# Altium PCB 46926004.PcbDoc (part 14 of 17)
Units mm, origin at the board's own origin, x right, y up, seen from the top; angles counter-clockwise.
Board outline 250 x 200 mm, 6 copper layers (Top Layer, INT1_GND, INT2_SIG, INT3_SIG, INT4_GND, Bottom Layer), stack 1.71 mm thick; 1450 components, 1293 nets, 5656 pads, 2307 vias.
Unrouted connection lines stored in the file: 2.
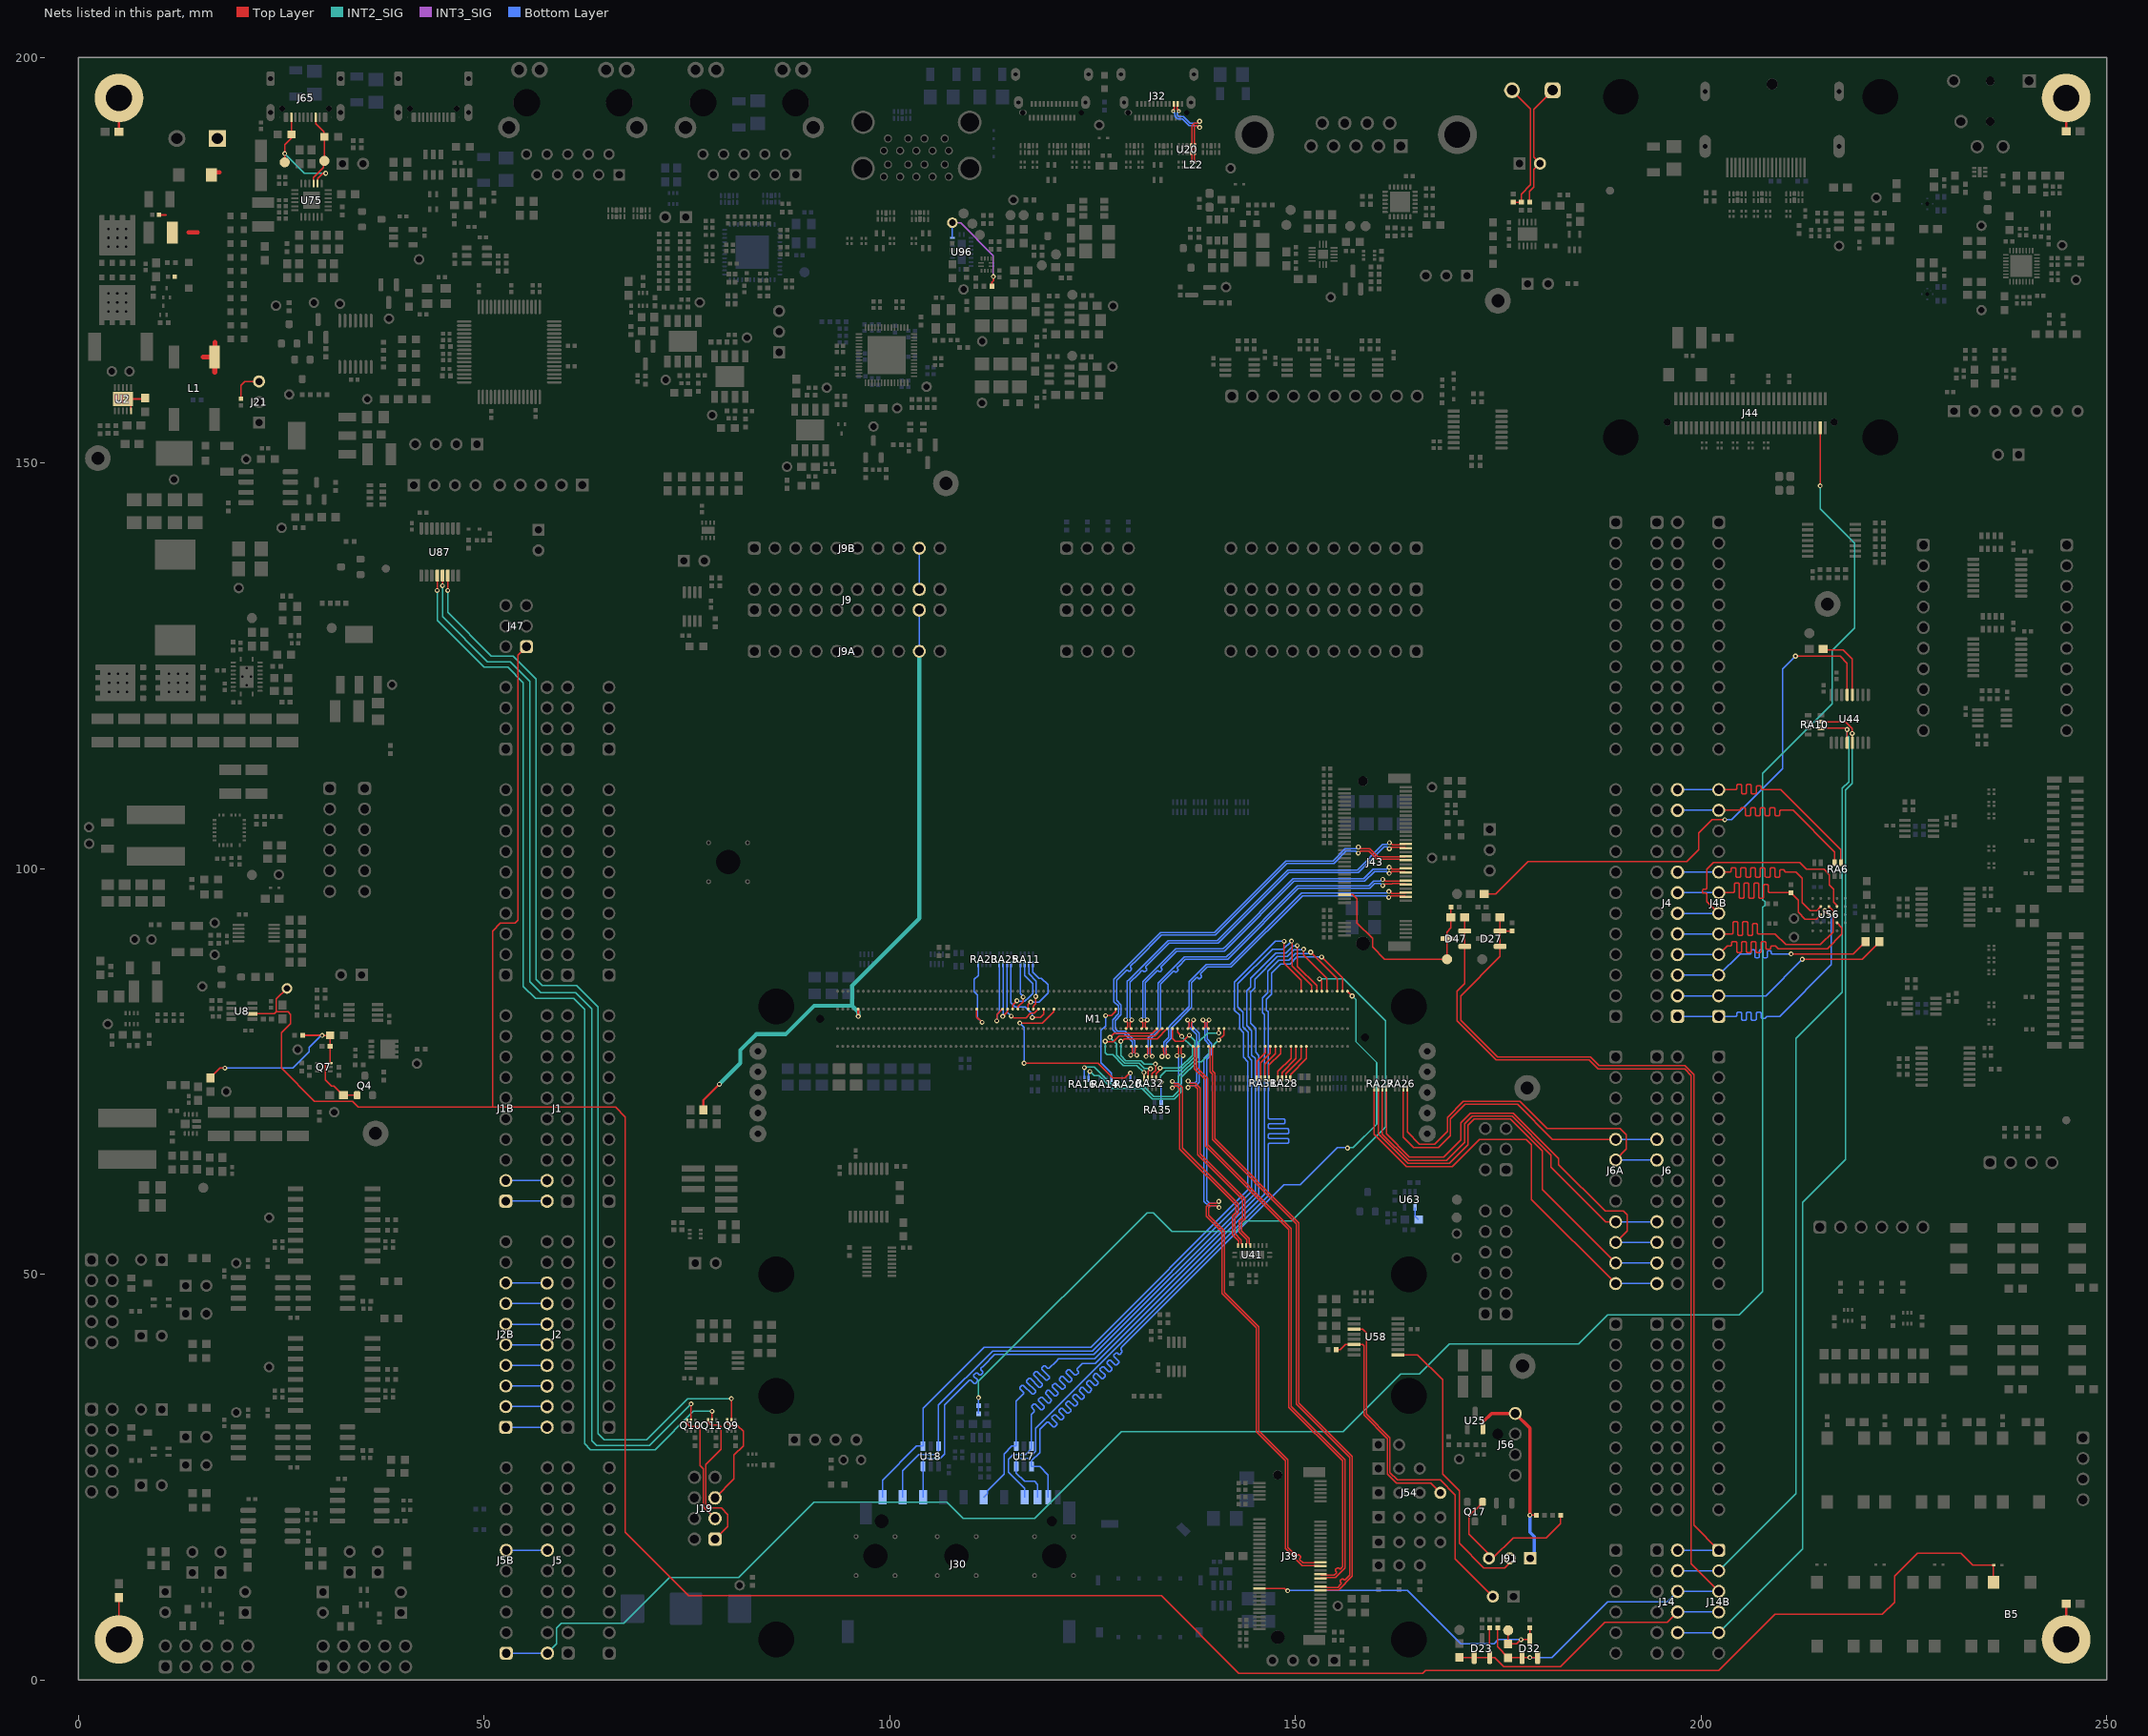
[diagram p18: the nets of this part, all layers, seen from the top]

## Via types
v1: diameter 0.6, hole 0.3, Top Layer to Bottom Layer, tented both sides, 2171 vias
v2: diameter 0.6, hole 0.3, Top Layer to Bottom Layer, 48 vias
v3: diameter 1, hole 0.5, Top Layer to Bottom Layer, tented both sides, 37 vias
v4: diameter 0.5, hole 0.2, Top Layer to Bottom Layer, tented both sides, 34 vias
v5: diameter 0.6, hole 0.3, Top Layer to Bottom Layer, tented bottom, 17 vias

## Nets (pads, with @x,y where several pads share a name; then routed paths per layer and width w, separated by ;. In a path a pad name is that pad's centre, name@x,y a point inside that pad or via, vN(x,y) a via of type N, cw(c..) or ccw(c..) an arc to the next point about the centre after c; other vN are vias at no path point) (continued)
OSPI_1_IO6_JMP: J4.21 J4B.11 RA6.4 | length 29.6
  Top Layer w0.15: J4B.11@202.17,107.2 204.69,107.2 204.765,107.2 204.885,107.32 204.885,107.408 205.005,107.528 205.365,107.528 205.485,107.408 205.485,106.638 205.605,106.518 205.965,106.518 206.085,106.638 206.085,107.408 206.205,107.528 206.565,107.528 206.685,107.408 206.685,106.638 206.805,106.518 207.165,106.518 207.285,106.638 207.285,107.408 207.405,107.528 207.765,107.528 207.885,107.408 207.885,106.638 208.005,106.518 208.365,106.518 208.485,106.638 208.485,107.408 208.605,107.528 208.965,107.528 209.085,107.408 209.085,106.655 209.205,106.535 209.565,106.535 209.685,106.655 209.685,107.08 209.805,107.2 210.895,107.2 211.325,107.2 216.45,102.075 RA6.4@216.45,100.725
  Bottom Layer w0.15: J4.21@197.09,107.2 J4B.11@202.17,107.2
OSPI_1_IO7: M1.B73 RA23.4 | length 9.7
  Top Layer w0.15: M1.B73@110.712,82.7 110.712,81.747 v1(111.391,81.068)
  Bottom Layer w0.15: RA23.4@110.9,88.25 110.9,86.862 110.4,86.362 110.4,84.848 110.827,84.421 110.827,81.632 v1(111.391,81.068)
OSPI_1_IO7_JMP: J4.23 J4B.12 RA6.3 | length 29.5
  Top Layer w0.15: J4B.12@202.17,109.74 204.19,109.74 204.265,109.74 204.385,109.86 204.385,110.266 204.505,110.386 204.865,110.386 204.985,110.266 204.985,109.353 205.105,109.233 205.465,109.233 205.585,109.353 205.585,110.266 205.705,110.386 206.065,110.386 206.185,110.266 206.185,109.353 206.305,109.233 206.665,109.233 206.785,109.353 206.785,110.097 206.905,110.217 207.265,110.217 207.385,110.097 207.385,109.86 207.505,109.74 208.592,109.74 209.798,109.74 217.213,102.325 217.213,100.762 RA6.3@217.25,100.725
  Bottom Layer w0.15: J4.23@197.09,109.74 J4B.12@202.17,109.74
PCIE/USB3_SEL: R194.2 U63.4 | length 1.7
  Bottom Layer w0.15: U63.4@164.75,58.248 164.75,57.183 165.175,56.758 R194.2@165.185,56.758
PCIE_1_CLK_N: J43.53 M1.D37 | length 43.5
  Top Layer w0.15: v1(133.548,76.847) 133.548,76.935 133.773,77.16 133.773,77.415 133.74,77.449 133.74,77.909 133.572,78.077 M1.D37@133.572,78.1 ; v1(161.512,97.2) 161.634,97.2 161.884,96.95 162.812,96.95 162.837,96.975 163.525,96.975 J43.53@163.6,97.05
  Bottom Layer w0.15: v1(133.548,76.847) 133.548,76.935 133.773,77.16 133.773,78.605 134.349,79.181 134.349,80.459 134.734,80.844 ; 134.734,80.865 134.734,80.844 ; v1(161.512,97.2) 161.422,97.2 161.199,96.977 156.578,96.977 156.576,96.975 150.748,96.975 141.963,88.19 139.001,88.19 136.91,86.099 136.91,83.02 134.734,80.844
PCIE_1_CLK_P: J43.55 M1.D36 | length 43.5
  Top Layer w0.15: M1.D36@134.207,78.1 134.207,78.077 134.04,77.909 134.04,77.574 134.073,77.54 134.073,77.16 134.298,76.935 v1(134.298,76.847) ; v1(161.5,96.45) 161.622,96.45 161.822,96.65 162.812,96.65 162.837,96.625 163.525,96.625 J43.55@163.6,96.55
  Bottom Layer w0.15: v1(134.298,76.847) 134.298,76.935 134.073,77.16 134.073,78.481 134.649,79.056 134.649,80.335 137.21,82.896 137.21,85.975 137.405,86.17 137.811,86.576 137.953,86.576 138.076,86.452 138.218,86.452 138.43,86.665 138.43,86.806 138.306,86.93 138.306,87.071 138.888,87.653 139.125,87.89 142.087,87.89 150.872,96.675 156.7,96.675 156.702,96.677 161.187,96.677 161.414,96.45 v1(161.5,96.45)
PCIE_1_CLKREQ: M1.C37 RA32.4 | length 15.6
  Top Layer w0.15: v1(126.562,78.727) 126.589,78.7 127.566,78.7 128.269,79.403 132.675,79.403 M1.C37@133.572,80.3 ; RA32.4@131.325,74.15 v1(131.325,74.884)
  INT2_SIG w0.15: v1(126.562,78.727) 126.562,77.31 126.815,77.057 127.468,77.057 128.775,75.75 130.459,75.75 v1(131.325,74.884)
PCIE_1_CLKREQ_JMP: D27.1 D27.2 J14.2 J14B.1 R198.2 R406.1 | length 112.7
  Top Layer w0.15: R406.1@175.221,93.985 D27.2@175.221,92.324 ; R198.2@176.693,92.35 176.666,92.324 D27.2@175.221,92.324 ; 199.1,23.402 199.1,19.08 J14B.1@202.18,16 ; 199.1,23.405 199.1,74.642 198.021,75.722 187.446,75.722 186.392,76.775 174.918,76.775 170.363,81.33 170.363,84.305 175.221,89.163 D27.1@175.221,90.424 D27.2@175.221,92.324
  Bottom Layer w0.15: J14.2@197.1,16 J14B.1@202.18,16
PCIE_1_L0_RX_N: J43.41 M1.C41 | length 44.4
  Top Layer w0.15: v1(130.975,81.35) 130.975,81.262 131.2,81.037 131.2,80.491 131.032,80.323 M1.C41@131.032,80.3 ; v1(161.562,100.175) 161.684,100.175 161.909,99.95 162.812,99.95 162.837,99.975 163.525,99.975 J43.41@163.6,100.05
  Bottom Layer w0.15: v1(130.975,81.35) 130.975,81.438 131.2,81.663 131.2,86.088 135.237,90.125 141.068,90.125 141.452,90.509 141.473,90.509 149.72,98.755 158.405,98.755 159.602,99.952 161.249,99.952 161.472,100.175 v1(161.562,100.175)
PCIE_1_L0_RX_P: J43.43 M1.C40 | length 44.4
  Top Layer w0.15: M1.C40@131.667,80.3 131.667,80.323 131.5,80.491 131.5,81.037 131.725,81.262 v1(131.725,81.35) ; v1(161.55,99.425) 161.672,99.425 161.897,99.65 162.812,99.65 162.837,99.625 163.525,99.625 J43.43@163.6,99.55
  Bottom Layer w0.15: v1(131.725,81.35) 131.725,81.438 131.5,81.663 131.5,85.963 132.556,87.019 132.962,87.425 133.104,87.425 133.216,87.313 133.357,87.313 133.569,87.526 133.569,87.667 133.457,87.779 133.457,87.92 133.875,88.338 135.362,89.825 141.235,89.825 141.598,90.187 141.598,90.209 149.844,98.455 158.529,98.455 159.726,99.652 161.237,99.652 161.464,99.425 v1(161.55,99.425)
PCIE_1_L0_TX_N: J43.47 M1.D40 | length 47.1
  Top Layer w0.15: v1(131.6,76.875) 131.6,76.988 131.8,77.188 131.8,77.911 131.667,78.044 M1.D40@131.667,78.1 ; v1(160.772,98.675) 160.858,98.675 161.085,98.448 161.788,98.448 161.79,98.45 162.812,98.45 162.837,98.475 163.525,98.475 J43.47@163.6,98.55
  Bottom Layer w0.15: v1(131.6,76.875) 131.6,76.963 131.825,77.188 131.825,79.127 133.073,80.375 133.073,85.901 136.322,89.15 141.504,89.15 141.801,89.447 141.822,89.447 150.241,97.865 152.221,97.865 ; 152.082,97.88 152.221,97.88 ; 152.206,97.88 152.221,97.865 ; v1(160.772,98.675) 160.683,98.675 160.46,98.452 159.626,98.452 159.038,97.865 152.221,97.865
PCIE_1_L0_TX_P: J43.49 M1.D39 | length 46.9
  Top Layer w0.15: M1.D39@132.302,78.1 M1.D39@132.302,78.1 132.1,77.9 132.1,77.188 132.325,76.963 132.35,76.963 v1(132.35,76.875) ; v1(160.761,97.925) 160.851,97.925 161.073,98.148 161.913,98.148 161.914,98.15 162.812,98.15 162.837,98.125 163.525,98.125 J43.49@163.6,98.05
  Bottom Layer w0.15: v1(132.35,76.875) 132.35,76.963 132.125,77.188 132.125,79.003 133.373,80.251 133.373,85.777 134.538,86.942 134.945,87.348 135.086,87.348 135.171,87.264 135.312,87.264 135.524,87.476 135.524,87.618 135.44,87.702 135.44,87.843 135.638,88.042 136.446,88.85 141.671,88.85 141.947,89.126 141.947,89.147 150.365,97.565 159.163,97.565 159.75,98.152 160.448,98.152 160.675,97.925 v1(160.761,97.925)
PCIE_1_L1_RX_N: J43.29 M1.C44 | length 47.8
  Top Layer w0.15: v1(129.075,81.35) 129.075,81.257 129.295,81.037 129.295,80.491 129.127,80.323 M1.C44@129.127,80.3 ; v1(161.587,103.2) 161.709,103.2 161.959,102.95 162.812,102.95 162.837,102.975 163.525,102.975 J43.29@163.6,103.05
  Bottom Layer w0.15: v1(129.075,81.35) 129.075,81.453 129.285,81.663 129.285,86.117 129.47,86.301 129.491,86.301 134.305,91.115 140.352,91.115 149.059,99.822 152.549,99.822 ; 152.41,99.837 152.549,99.837 ; 152.534,99.837 152.549,99.822 ; v1(161.587,103.2) 161.499,103.2 161.274,102.975 160.776,102.975 157.623,99.822 152.549,99.822
PCIE_1_L1_RX_P: J43.31 M1.C43 | length 47.6
  Top Layer w0.15: M1.C43@129.762,80.3 129.762,80.323 129.595,80.491 129.595,81.032 129.825,81.262 v1(129.825,81.35) ; v1(161.575,102.45) 161.697,102.45 161.897,102.65 162.812,102.65 162.837,102.625 163.525,102.625 J43.31@163.6,102.55
  Bottom Layer w0.15: v1(129.825,81.35) 129.825,81.453 129.615,81.663 129.615,86.001 130.641,87.027 131.047,87.433 131.189,87.433 131.32,87.302 131.462,87.302 131.674,87.514 131.674,87.655 131.542,87.787 131.542,87.928 132.247,88.633 134.429,90.815 140.476,90.815 149.183,99.522 157.747,99.522 160.901,102.675 161.262,102.675 161.487,102.45 v1(161.575,102.45)
PCIE_1_L1_TX_N: J43.35 M1.D43 | length 56.1
  Top Layer w0.15: v1(129.7,77.018) 129.7,77.105 129.925,77.33 129.925,77.659 129.93,77.664 129.93,77.909 129.762,78.077 M1.D43@129.762,78.1 ; v1(157.749,102.675) 157.835,102.675 158.062,102.448 158.336,102.448 158.338,102.45 159.144,102.45 160.144,101.45 162.812,101.45 162.837,101.475 163.525,101.475 J43.35@163.6,101.55
  Bottom Layer w0.15: v1(129.7,77.018) 129.7,77.105 129.925,77.33 129.925,78.649 128.923,79.652 127.989,79.652 127.475,80.165 127.475,81.399 128.215,82.139 128.215,83.062 127.64,83.637 127.64,86.361 133.394,92.115 139.986,92.115 148.836,100.965 154.645,100.965 156.132,102.452 157.436,102.452 157.659,102.675 v1(157.749,102.675)
PCIE_1_L1_TX_P: J43.37 M1.D42 | length 56.1
  Top Layer w0.15: M1.D42@130.397,78.1 130.397,78.077 130.23,77.909 130.23,77.54 130.225,77.535 130.225,77.33 130.45,77.105 v1(130.45,77.018) ; v1(157.737,101.925) 157.827,101.925 158.05,102.148 158.461,102.148 158.463,102.15 159.02,102.15 160.02,101.15 162.812,101.15 162.837,101.125 163.525,101.125 J43.37@163.6,101.05
  Bottom Layer w0.15: v1(130.45,77.018) 130.45,77.105 130.225,77.33 130.225,78.774 129.047,79.952 128.113,79.952 127.775,80.289 127.775,81.275 128.515,82.015 128.515,83.186 127.94,83.761 127.94,86.236 128.787,87.084 129.194,87.49 129.335,87.49 129.453,87.373 129.594,87.373 129.806,87.585 129.806,87.727 129.689,87.844 129.689,87.985 130.503,88.799 133.519,91.815 140.111,91.815 148.961,100.665 154.769,100.665 156.256,102.152 157.424,102.152 157.651,101.925 v1(157.737,101.925)
PCIE_1_RESET#: M1.C38 RA32.3 | length 15
  Top Layer w0.15: v1(127.141,79.225) 127.663,79.746 132.383,79.746 M1.C38@132.937,80.3 ; RA32.3@131.825,74.15 131.85,74.175 131.85,75.021 132.14,75.311 v1(132.14,75.333)
  INT2_SIG w0.15: v1(127.141,79.225) 127.995,78.371 127.995,77.011 128.956,76.05 130.714,76.05 131.354,75.409 132.064,75.409 v1(132.14,75.333)
PCIE_1_RESET#_3V: R199.1 U44.13 | length 69.3
  Top Layer w0.15: R199.1@173.246,96.9 174.691,96.9 178.652,100.861 198.236,100.861 199.7,102.325 199.7,104.385 201.351,106.036 v1(202.93,106.036) ; v1(211.635,126.204) 217.146,126.204 218,125.35 U44.13@218,121.725
  Bottom Layer w0.15: v1(202.93,106.036) 203.734,106.036 210.052,112.354 210.052,124.621 v1(211.635,126.204)
PCIE_1_RESET#_JMP: J14.4 J14B.2 RA10.2 U44.4 | length 120.4
  Top Layer w0.15: RA10.2@214.775,117.325 217.714,117.325 217.878,117.161 v1(218,117.161) U44.4@218,115.525
  INT2_SIG w0.15: J14B.2@202.18,13.46 211.7,22.98 211.7,79.1 217.4,84.8 217.4,109.9 218.2,110.7 218.2,116.2 218,116.4 v1(218,117.161)
  Bottom Layer w0.15: J14.4@197.1,13.46 J14B.2@202.18,13.46
PCIE_2_CLK_N: J39.53 M1.D28 | length 77.1
  Top Layer w0.15: M1.D28@139.287,78.1 139.287,78.077 139.455,77.909 139.455,74.97 139.748,74.677 139.748,66.608 150.125,56.231 150.125,33.99 156.7,27.415 156.7,12.925 156.4,12.625 156.137,12.362 155.995,12.362 155.878,12.479 155.737,12.479 155.524,12.267 155.524,12.125 155.642,12.008 155.642,11.867 155.589,11.814 155.2,11.425 153.888,11.425 153.863,11.45 153.175,11.45 J39.53@153.1,11.525
PCIE_2_CLK_P: J39.55 M1.D27 | length 77.1
  Top Layer w0.15: M1.D27@139.922,78.1 139.922,78.077 139.755,77.909 139.755,75.095 140.048,74.801 140.048,66.732 150.425,56.355 150.425,34.114 157,27.539 157,12.801 155.324,11.125 153.888,11.125 153.863,11.1 153.175,11.1 J39.55@153.1,11.025
PCIE_2_CLKREQ: M1.C34 RA32.1 | length 10.2
  Top Layer w0.15: RA32.1@132.825,74.15 132.825,74.715 133.312,75.201 v1(133.312,75.427) ; M1.C34@135.477,80.3 135.477,79.846 v1(135.986,79.337)
  INT2_SIG w0.15: v1(133.312,75.427) 135.717,75.427 137.285,76.994 137.285,78.039 v1(135.986,79.337)
PCIE_2_CLKREQ_JMP: D23.1 D23.2 J14.8 J14B.4 R182.2 R308.1 | length 38.9
  Top Layer w0.15: R308.1@170.2,2.79 D23.1@172.037,2.79 D23.2@173.937,2.79 ; R182.2@173.937,6.423 D23.2@173.937,2.79 ; J14.8@197.1,8.38 195.848,7.128 188.153,7.128 182.675,1.65 175.683,1.65 174.543,2.79 D23.2@173.937,2.79
  Bottom Layer w0.15: J14.8@197.1,8.38 J14B.4@202.18,8.38
PCIE_2_L0_RX_N: J39.41 M1.C29 | length 79
  Top Layer w0.15: v1(138.6,81.35) 138.6,81.228 138.82,81.009 138.82,80.491 138.652,80.323 M1.C29@138.652,80.3 ; v1(140.578,58.236) 140.475,58.236 140.265,58.446 139.527,58.446 139.302,58.221 139.302,57.272 141.225,55.349 141.225,47.78 145.456,43.549 145.456,30.745 149.05,27.151 149.05,16.315 149.8,15.565 150.038,15.327 150.18,15.327 150.282,15.428 150.423,15.428 150.635,15.216 150.635,15.075 150.533,14.973 150.533,14.832 150.94,14.425 152.312,14.425 152.337,14.45 153.025,14.45 J39.41@153.1,14.525
  Bottom Layer w0.15: v1(138.6,81.35) 138.6,81.262 138.825,81.037 138.825,78.89 139.385,78.33 139.385,77.283 138.743,76.641 138.743,58.996 139.282,58.457 140.265,58.457 140.486,58.236 v1(140.578,58.236)
PCIE_2_L0_RX_P: J39.43 M1.C28 | length 79.1
  Top Layer w0.15: M1.C28@139.287,80.3 139.287,80.323 139.12,80.491 139.12,80.998 139.35,81.228 v1(139.35,81.35) ; v1(140.556,58.985) 140.468,58.985 140.228,58.746 139.403,58.746 139.002,58.345 139.002,57.148 140.925,55.225 140.925,47.656 145.156,43.425 145.156,30.621 148.75,27.027 148.75,16.191 150.816,14.125 152.312,14.125 152.337,14.1 153.025,14.1 J39.43@153.1,14.025
  Bottom Layer w0.15: v1(139.35,81.35) 139.35,81.262 139.125,81.037 139.125,79.014 139.685,78.454 139.685,77.158 139.043,76.517 139.043,59.12 139.406,58.757 140.243,58.757 140.472,58.985 v1(140.556,58.985)
PCIE_2_L0_TX_N: J39.47 M1.D31 | length 75.4
  Top Layer w0.15: M1.D31@137.382,78.1 137.382,78.077 137.55,77.909 137.55,75.35 138.87,74.029 138.87,65.862 149.2,55.532 149.2,33.63 155.8,27.03 155.8,13.937 155.715,13.852 155.576,13.713 155.435,13.713 155.318,13.831 155.176,13.831 154.964,13.618 154.964,13.477 155.081,13.36 155.081,13.218 155.028,13.165 154.788,12.925 153.888,12.925 153.863,12.95 153.175,12.95 J39.47@153.1,13.025
PCIE_2_L0_TX_P: J39.49 M1.D30 | length 75.4
  Top Layer w0.15: M1.D30@138.017,78.1 138.017,78.077 137.85,77.909 137.85,75.474 139.17,74.154 139.17,65.987 149.5,55.656 149.5,33.754 156.1,27.154 156.1,13.813 154.912,12.625 153.888,12.625 153.863,12.6 153.175,12.6 J39.49@153.1,12.525
PCIE_2_L1_RX_N: M1.C32 U41.16 | length 34.6
  Top Layer w0.15: v1(136.7,81.35) 136.7,81.228 136.915,81.014 136.915,80.491 136.747,80.323 M1.C32@136.747,80.3 ; v1(136.775,73.825) 136.84,73.825 137.088,73.578 137.65,73.578 138.248,72.98 138.248,64.864 143.75,59.362 143.75,56.822 143.363,56.436 143.363,55.359 144.323,54.399 144.323,53.83 144.423,53.73 U41.16@144.423,53.55
  Bottom Layer w0.15: v1(136.7,81.35) 136.7,81.247 136.91,81.037 136.91,80.491 137.82,79.581 137.82,73.795 137.618,73.593 137.088,73.593 136.855,73.825 v1(136.775,73.825)
PCIE_2_L1_RX_P: M1.C31 U41.17 | length 34.7
  Top Layer w0.15: v1(136.766,73.03) 136.832,73.03 137.079,73.278 137.526,73.278 137.948,72.856 137.948,64.74 143.45,59.238 143.45,56.947 143.063,56.56 143.063,55.235 144.023,54.275 144.023,53.83 143.923,53.73 U41.17@143.923,53.55 ; M1.C31@137.382,80.3 137.382,80.323 137.215,80.491 137.215,81 137.45,81.235 v1(137.45,81.35)
  Bottom Layer w0.15: v1(136.766,73.03) 136.847,73.03 137.079,73.263 137.754,73.263 138.15,73.658 138.15,79.718 137.24,80.628 137.24,81.037 137.45,81.247 v1(137.45,81.35)
PCIE_2_L1_TX_N: M1.D34 U41.18 | length 30
  Top Layer w0.15: v1(134.825,73.775) 134.89,73.775 135.138,73.528 135.572,73.528 136.05,73.05 136.05,65.598 142.972,58.676 142.972,57.524 142.523,57.076 142.523,55.026 143.323,54.226 143.323,53.83 143.423,53.73 U41.18@143.423,53.55 ; v1(135.4,76.95) 135.4,77.038 135.625,77.263 135.625,77.909 135.477,78.057 M1.D34@135.477,78.1
  Bottom Layer w0.15: v1(134.825,73.775) 134.905,73.775 135.138,73.543 135.468,73.543 135.61,73.685 135.61,76.637 135.4,76.847 v1(135.4,76.95)
PCIE_2_L1_TX_P: M1.D33 U41.19 | length 30.1
  Top Layer w0.15: v1(134.816,72.98) 134.882,72.98 135.129,73.228 135.448,73.228 135.75,72.926 135.75,65.473 142.672,58.552 142.672,57.648 142.223,57.2 142.223,54.901 143.023,54.101 143.023,53.83 142.923,53.73 U41.19@142.923,53.55 ; M1.D33@136.112,78.1 136.112,78.096 135.925,77.909 135.925,77.263 136.15,77.038 v1(136.15,76.95)
  Bottom Layer w0.15: v1(134.816,72.98) 134.897,72.98 135.129,73.213 135.604,73.213 135.94,73.548 135.94,76.637 136.15,76.847 v1(136.15,76.95)
PCIE_2_RESET#: M1.C35 RA35.2 | length 15.2
  Top Layer w0.15: M1.C35@134.842,80.3 134.842,79.087 135.222,78.707 136.163,78.707 v1(136.926,79.47)
  INT2_SIG w0.15: v1(133.447,73.697) 133.394,73.75 133.394,74.447 134.042,75.095 135.81,75.095 137.585,76.87 137.585,78.811 v1(136.926,79.47)
  Bottom Layer w0.15: RA35.2@133.447,71.069 v1(133.447,73.697)
PCIE_2_RESET#_3V: R183.1 U44.12 | length 8.2
  Top Layer w0.15: R183.1@215.05,127.1 215.175,126.975 217.5,126.975 218.65,125.825 U44.12@218.65,121.725
PCIE_2_RESET#_JMP: J14.10 J14B.5 RA10.3 U44.5 | length 129
  Top Layer w0.15: RA10.3@214.775,118.125 217.779,118.125 218.625,117.279 v1(218.625,116.675) 218.638,116.662 U44.5@218.638,115.238
  INT2_SIG w0.15: J14B.5@202.18,5.84 212.5,16.16 212.5,58.856 217.8,64.156 217.8,109.7 218.625,110.525 v1(218.625,116.675)
  Bottom Layer w0.15: J14.10@197.1,5.84 J14B.5@202.18,5.84
PCIE_WAKE#: M1.C36 RA32.2 | length 14.8
  Top Layer w0.15: v1(128.478,78.728) 128.591,78.728 128.906,79.043 132.95,79.043 M1.C36@134.207,80.3 ; RA32.2@132.325,74.15 132.325,74.729 132.76,75.163 132.76,75.902 v1(132.744,75.917)
  INT2_SIG w0.15: v1(128.478,78.728) 128.48,78.726 128.48,77.633 128.48,76.95 129.08,76.35 130.95,76.35 131.383,75.917 v1(132.744,75.917)
PCIE_WAKE#_JMP: D32.1 D32.2 D47.1 D47.2 J14.6 J14B.3 R301.1 R341.1 R418.1 | length 144.7
  Top Layer w0.15: R341.1@170.871,93.985 D47.2@170.871,92.324 D47.1@170.871,90.424 170.871,85.869 169.921,84.919 169.921,81.252 174.747,76.426 186.165,76.426 187.291,75.3 194.105,75.3 194.115,75.31 197.525,75.31 197.535,75.3 197.987,75.3 198.778,74.509 198.778,20.309 ; R418.1@174.928,6.423 174.928,4.087 176.225,2.79 R301.1@176.225,2.74 176.256,2.771 D32.1@177.95,2.771 ; D32.2@179.85,2.771 v1(178.9,2.771) D32.1@178.11,2.771 ; 198.778,20.306 198.778,14.322 J14B.3@202.18,10.92 ; D32.1@177.95,2.771 177.95,2.931 D32.1@178.11,2.771 ; D32.1@177.95,2.771 D32.1@178.11,2.771
  Bottom Layer w0.15: v1(178.9,2.771) 181.625,2.771 188.504,9.65 195.83,9.65 J14.6@197.1,10.92 J14B.3@202.18,10.92
PD_CC1: C290.1 J65.A5 U75.15 X91.1 | length 9.2
  Top Layer w0.15: U75.15@28.975,184.45 28.975,185.175 30.2,186.4 30.2,187.125 X91.1@30.325,187.25 C290.1@30.325,190.225 30.245,190.305 30.245,190.837 29.25,191.832 J65.A5@29.25,192.622
PD_CC2: C291.1 J65.B5 U75.14 X92.1 | length 13.8
  Top Layer w0.15: X92.1@25.425,187.08 25.425,189.25 26.25,190.075 26.25,190.75 J65.B5@26.25,192.622 ; U75.14@29.475,184.45 29.475,185.075 30.125,185.725 v1(30.475,185.725)
  INT2_SIG w0.15: v1(25.425,188.145) 27.845,185.725 v1(30.475,185.725)
PEWAKE_M2B#: D32.3 J39.54 R301.2 R322.2 X64.1 | length 41.2
  Top Layer w0.15: J39.54@145.55,11.275 148.658,11.275 148.928,11.005 v1(149.05,11.005) ; X64.1@176.225,5.998 R301.2@176.225,4.44 177.274,4.44 v1(177.805,4.971) D32.3@178.9,4.971 R322.2@178.9,6.428
  Bottom Layer w0.15: v1(149.05,11.005) 149.095,11.05 163.793,11.05 170.378,4.465 174.488,4.465 174.994,4.971 v1(177.805,4.971)
PEWAKE_M2M#: D47.3 J43.54 R341.2 R417.2 X69.1 | length 25
  Top Layer w0.15: J43.54@156.05,96.8 157.07,96.8 157.6,96.27 157.6,93.296 159.5,91.396 159.5,90.345 161.009,88.837 X69.1@168.694,88.837 168.694,88.9 168.694,91.351 D47.3@168.671,91.374 168.671,92.189 169.171,92.689 R341.2@169.171,93.985 169.171,95.265 R417.2@169.166,95.27
PGND: C2.1 C3.2 C6.1 C7.2 D1.1 J17.1 J21.3 L1.1 R3.1 U2.5 U2.11 | length 16.9
  Top Layer w0.15: U2.11@5.477,157.886 5.676,157.886 6.477,157.084 U2.5@6.477,156.438 ; C7.2@20.025,157.925 20.025,159.571 20.519,160.065 J21.3@22.26,160.065
  Top Layer w0.25: U2.11@5.676,157.886 8.101,157.886 R3.1@8.227,158.012 ; C3.2@10.025,180.6 10.75,180.6
  Top Layer w0.5: 13.575,178.425 14.725,178.425 ; D1.1@16.13,185.85 17.38,185.85
  Top Layer w0.6: 15.373,163.072 L1.1@16.79,163.072 ; 16.8,161.197 16.8,163.038 16.812,163.05 16.812,164.87
PWM-MODE: J76.2 U58.11 | length 43.8
  Top Layer w0.15: U58.11@157.237,43.253 158.277,43.253 158.736,42.795 158.736,32.764 161.65,29.85 161.65,25.583 162.564,24.669 167.836,24.669 169.7,22.805 169.7,14.914 J76.2@174.34,10.274
PWM_1: M1.C25 RA16.4 | length 24.4
  Top Layer w0.15: v1(140.554,78.884) 141.192,79.522 M1.C25@141.192,80.3
  INT2_SIG w0.15: v1(124.67,75.021) 125.179,74.512 125.774,74.512 127.401,72.885 131.064,72.885 132.35,71.6 135.063,71.6 135.925,72.462 135.925,74.239 137.886,76.2 138.45,76.2 139.35,77.1 139.35,77.69 140.544,78.884 v1(140.554,78.884)
  Bottom Layer w0.15: RA16.4@124.496,74.072 124.496,74.847 v1(124.67,75.021)
PWM_1_JMP: J1.2 J1B.1 | length 5.1
  Bottom Layer w0.15: J1B.1@52.68,59.02 J1.2@57.76,59.02
PWM_2: M1.C26 RA16.3 | length 25.4
  Top Layer w0.15: v1@140.557,79.759 M1.C26@140.557,80.3
  INT2_SIG w0.15: v1(123.996,75.474) 124.068,75.546 125.199,75.546 127.559,73.185 131.262,73.185 132.547,71.9 134.917,71.9 135.625,72.608 135.625,74.42 138.005,76.799 138.005,78.593 139.17,79.758 v1(140.558,79.758)
  Bottom Layer w0.15: RA16.3@123.996,74.072 v1(123.996,75.474)
PWM_2_JMP: J1.4 J1B.2 | length 5.1
  Bottom Layer w0.15: J1B.2@52.68,61.56 J1.4@57.76,61.56
PWM_3_DSI: M1.B46 RA14.4 | length 10.3
  Top Layer w0.15: v1(126.6,81.882) 127.332,81.882 127.857,82.407 M1.B46@127.857,82.7
  Bottom Layer w0.15: v1(126.6,81.882) 126.6,80.618 126.037,80.056 126.037,76.077 127.325,74.789 RA14.4@127.325,74.072
PWM_3_DSI_JMP: J5.2 J5B.1 J44.58 | length 289.2
  Top Layer w0.15: v1(214.672,147.2) J44.58@214.672,154.35
  INT2_SIG w0.15: J5.2@57.81,3.3 58.959,4.449 58.959,6.409 59.53,6.98 67.205,6.98 72.86,12.635 81.375,12.635 90.64,21.9 107.066,21.9 109.061,19.905 117.855,19.905 128.55,30.6 155.9,30.6 163,37.7 165.266,37.7 168.97,41.405 184.905,41.405 188.5,45 204.7,45 207.6,47.9 207.6,95.233 207.85,95.483 207.85,95.917 207.6,96.167 207.6,111.754 216.152,120.306 216.152,126.898 218.9,129.647 218.9,140.151 214.672,144.378 v1(214.672,147.2)
  Bottom Layer w0.15: J5B.1@52.73,3.3 J5.2@57.81,3.3
PWM_4_DP: M1.B58 RA20.3 | length 25.1
  Top Layer w0.15: v1(116.025,80.977) 118.813,80.977 120.237,82.401 120.237,82.687 M1.B58@120.243,82.694 ; v1(116.553,76.025) 125.664,76.025 127.489,74.2 128.966,74.2 129.574,74.808 v1(129.65,74.808)
  Bottom Layer w0.15: v1(116.025,80.977) 116.553,80.449 v1(116.553,76.025) ; RA20.3@129.65,74.072 v1(129.65,74.808)
PWM_4_DP_JMP: J5.12 J5B.6 | length 5.1
  Bottom Layer w0.15: J5B.6@52.73,16 J5.12@57.81,16
PWM_OUT: J91.2 U58.1 | length 36.3
  Top Layer w0.15: U58.1@162.637,40.077 165.062,40.077 168.144,36.995 168.144,25.381 170.2,23.325 170.2,16.837 173.225,13.813 175.793,13.813 176.88,14.9 J91.2@176.88,15.026
PWM_OUT_3WIRE: J91.3 Q17.1 R265.2 | length 20
  Top Layer w0.15: Q17.1@173.075,21.95 173.075,21.875 171.388,20.188 171.388,17.978 174.34,15.026 176.85,17.535 180.924,17.535 182.689,19.3 R265.2@182.689,20.306
PWM_OUT_4WIRE: J56.4 J91.1 R264.2 U25.2 | length 24.9
  Top Layer w0.15: v1(178.9,20.306) R264.2@179.694,20.306
  Top Layer w0.4: U25.2@173.1,30.925 173.1,31.78 174.175,32.855 J56.4@177.1,32.855 178.9,31.055 v1(178.9,20.306)
  Bottom Layer w0.4: v1(178.9,20.306) 178.9,18.229 179.42,17.709 J91.1@179.42,15.026
PWR_1V8_MOCI: J9.17 J9A.9 M1.B96 R286.2 | length 80.1
  Top Layer w0.25: R286.2@77.03,70.25 77.03,71.47 v1(78.995,73.435) ; M1.B96@96.107,82.7 96.116,82.691 96.116,81.82 v1(96.125,81.811)
  INT2_SIG w0.5: v1(78.995,73.435) 81.584,76.023 81.584,77.632 83.552,79.6 87.16,79.6 90.675,83.115 95.35,83.115 ; v1@96.125,81.784 v1(96.125,81.811) 96.125,82.34 95.35,83.115 ; J9A.9@103.64,126.81 103.64,93.876 95.35,85.586 95.35,83.115
  Bottom Layer w0.15: J9A.9@103.64,126.81 J9.17@103.64,131.89
PWR_1V8_MOCI_JMP: J9.18 J9B.9 | length 5.1
  Bottom Layer w0.15: J9.18@103.64,134.43 J9B.9@103.64,139.51
PWR_BTN#: B5.3 D8.2 J47.1 U8.2 X22.1 | length 357.6
  Top Layer w0.15: U8.2@21.465,82.125 24.168,82.125 24.393,82.35 ; X22.1@25.709,85.25 24.4,83.941 24.4,82.357 24.393,82.35 ; J47.1@55.22,127.36 54.2,126.34 54.2,93.675 53.803,93.278 52.018,93.278 51.07,92.33 51.07,70.6 ; B5.3@236.039,12.037 236.039,14.138 D8.2@236.063,14.162 233.513,14.162 232.025,15.65 226.65,15.65 223.825,12.825 223.825,9.575 222.35,8.1 209.1,8.1 202.2,1.2 166.063,1.2 165.713,0.85 143.018,0.85 133.468,10.4 75.214,10.4 67.4,18.214 67.4,69.4 66.2,70.6 51.07,70.6 ; 24.393,82.35 25.845,82.35 26.16,82.035 26.16,80.922 25.041,79.803 25.041,75.42 29.111,71.35 33.763,71.35 34.513,70.6 51.07,70.6
PWR_BTN#_1V8: Q10.5 U87.5 | length 135
  Top Layer w0.15: v1(44.865,134.876) U87.5@44.865,136.136 ; Q10.5@75.509,32.031 v1(75.509,34.042)
  INT2_SIG w0.15: v1(44.865,134.876) 44.865,131.075 50.44,125.5 53.206,125.5 55.62,123.086 55.62,86.08 56.985,84.715 61.285,84.715 63.3,82.7 63.3,29.5 63.885,28.915 70.382,28.915 v1(75.509,34.042)
PWR_BTN_MICO#: J19.3 Q10.6 | length 14.1
  Top Layer w0.15: Q10.6@75.009,32.031 75.009,31.632 75.391,31.25 76.391,31.25 76.616,31.025 76.616,26.455 77.04,26.032 77.04,21.334 J19.3@78.469,19.905
PWR_EN: C50.1 Q4.1 Q7.3 R28.2 R33.1 R60.1 R465.1 | length 30.4
  Top Layer w0.15: R33.1@16.3,74.225 16.3,74.275 17.45,75.425 v1(18.05,75.425) ; v1(30.033,79.443) C50.1@31.033,79.443 ; R60.1@31.025,78.125 R60.1@31.04,78.125 ; C50.1@31.025,79.45 C50.1@31.033,79.443 ; Q4.1@34.35,72.075 R28.2@32.65,72.075 32.6,72.075 31.475,73.2 31.174,73.2 30.425,73.949 30.425,75.925 30.55,76.05 Q7.3@31.04,76.05 R60.1@31.04,78.125 ; C50.1@31.033,79.443 31.04,79.435 R60.1@31.04,78.125
  Top Layer w0.25: R465.1@27.645,79.45 27.649,79.446 30.029,79.446 v1(30.033,79.443)
  Bottom Layer w0.15: v1(18.05,75.425) 26.416,75.425 28.426,77.435 28.426,77.945 29.924,79.443 v1(30.033,79.443)
QSPI_1_CS1#: M1.B66 RA11.3 | length 7.6
  Top Layer w0.15: M1.B66@115.157,82.7 115.157,83.213 v1(115.666,83.722)
  Bottom Layer w0.15: v1(115.666,83.722) 115.727,83.661 116.657,83.661 117.134,84.138 117.6,84.604 117.6,85.868 116.634,86.834 RA11.3@116.634,88.25
QSPI_1_CS1#_JMP: J4.5 J4B.3 R228.2 | length 29
  Top Layer w0.15: v1(211.093,89.498) 218.736,89.498 219.788,90.55 219.825,90.55 220.25,90.975 R228.2@220.25,91.012
  Bottom Layer w0.15: J4.5@197.09,86.88 201.5,86.88 201.73,87.11 J4B.3@201.73,87.32 ; J4B.3@202.17,86.88 204.788,89.498 205.967,89.498 206.042,89.498 206.142,89.598 206.142,89.923 206.242,90.023 206.542,90.023 206.642,89.923 206.642,89.087 206.742,88.987 207.042,88.987 207.142,89.087 207.142,89.923 207.242,90.023 207.542,90.023 207.642,89.923 207.642,89.087 207.742,88.987 208.042,88.987 208.142,89.087 208.142,89.789 208.242,89.889 208.542,89.889 208.642,89.789 208.642,89.598 208.742,89.498 210.128,89.498 v1(211.093,89.498)
QSPI_1_CS2#: M1.B62 RA11.2 | length 6.1
  Top Layer w0.15: M1.B62@117.697,82.7 117.697,83.046 118,83.349 v1(118,84.255)
  Bottom Layer w0.15: RA11.2@117.134,88.25 117.134,87.05 118.05,86.134 118.05,84.305 v1(118,84.255)
QSPI_1_CS2#_JMP: J4.3 J4B.2 R229.2 | length 27.7
  Top Layer w0.15: v1(212.481,88.837) 219.862,88.837 222,90.975 R229.2@222,91.025
  Bottom Layer w0.15: J4.3@197.09,84.34 200.97,84.34 J4B.2@202.17,84.34 207.984,84.34 v1(212.481,88.837)
QSPI_1_DQS: M1.B63 RA11.1 | length 8.1
  Top Layer w0.15: M1.B63@117.062,82.7 117.062,83.241 v1(117.392,83.571)
  Bottom Layer w0.15: v1(117.392,83.571) 118.387,83.571 119.48,84.663 119.48,85.729 118.706,86.503 118.364,86.503 117.634,87.233 RA11.1@117.634,88.25
QSPI_1_DQS_JMP: J4.1 J4B.1 U56.C3 | length 34
  Top Layer w0.15: v1(215.25,94.85) U56.C3@215.75,94.35
  Bottom Layer w0.15: J4.1@197.09,81.8 J4B.1@202.17,81.8 204.19,81.8 204.265,81.8 204.385,81.92 204.385,82.222 204.505,82.342 204.865,82.342 204.985,82.222 204.985,81.46 205.105,81.34 205.465,81.34 205.585,81.46 205.585,82.222 205.705,82.342 206.065,82.342 206.185,82.222 206.185,81.46 206.305,81.34 206.665,81.34 206.785,81.46 206.785,82.222 206.905,82.342 207.265,82.342 207.385,82.222 207.385,81.648 207.505,81.528 207.865,81.528 207.985,81.648 207.985,81.68 208.105,81.8 208.241,81.8 209.7,81.8 216.067,88.167 216.067,94.033 v1(215.25,94.85)
QSPI_1_IO0: M1.B68 RA25.4 | length 8.9
  Top Layer w0.15: v1(113.193,81.235) 113.193,82.006 M1.B68@113.887,82.7
  Bottom Layer w0.15: v1(113.193,81.235) 113.193,82.043 113.525,82.375 113.525,88.2 RA25.4@113.475,88.25
QSPI_1_IO0_JMP: J4.9 J4B.5 U56.D3 | length 32.3
  Top Layer w0.15: J4B.5@202.17,91.96 203.739,91.96 203.814,91.96 203.934,92.08 203.934,93.339 204.054,93.459 204.414,93.459 204.534,93.339 204.534,91.87 204.654,91.75 205.014,91.75 205.134,91.87 205.134,93.339 205.254,93.459 205.614,93.459 205.734,93.339 205.734,91.87 205.854,91.75 206.214,91.75 206.334,91.87 206.334,93.142 206.454,93.262 206.814,93.262 206.934,93.142 206.934,92.08 207.054,91.96 207.77,91.96 209.134,91.96 210.454,90.64 214.715,90.64 216.25,92.175 216.25,94.85 U56.D3@215.75,95.35
  Bottom Layer w0.15: J4.9@197.09,91.96 J4B.5@202.17,91.96
QSPI_1_IO1: M1.B67 RA25.3 | length 7.6
  Top Layer w0.15: v1(113.925,81.8) 114.522,82.397 M1.B67@114.522,82.7
  Bottom Layer w0.15: v1(113.925,81.8) 113.975,81.85 RA25.3@113.975,88.25
QSPI_1_IO1_JMP: J4.11 J4B.6 U56.D2 | length 32.3
  Top Layer w0.15: J4B.6@202.17,94.5 200.7,95.97 200.7,96.8 200.7,96.875 200.6,96.975 200.263,96.975 200.163,97.075 200.163,97.375 200.263,97.475 200.6,97.475 200.7,97.575 200.7,98.1 200.7,99.925 201.53,100.755 212.178,100.755 213.008,99.925 215.155,99.925 215.83,99.25 215.83,97.978 216.35,97.458 216.35,95.88 216.712,95.519 216.712,95.388 U56.D2@216.75,95.35
  Bottom Layer w0.15: J4.11@197.09,94.5 J4B.6@202.17,94.5
QSPI_1_IO2: M1.B61 RA25.2 | length 10.5
  Top Layer w0.15: v1(114.975,81.82) 115.093,81.82 115.288,81.625 116.804,81.625 117.354,82.175 117.808,82.175 M1.B61@118.332,82.7 M1.B61@118.332,82.7
  Bottom Layer w0.15: RA25.2@114.475,88.25 114.475,82.32 v1(114.975,81.82)
QSPI_1_IO2_JMP: J4.13 J4B.7 R238.2 U56.C4 | length 32.3
  Top Layer w0.15: J4B.7@202.17,97.04 202.704,97.04 203.979,97.04 204.099,97.16 204.099,98.133 204.219,98.253 204.579,98.253 204.699,98.133 204.699,96.499 204.819,96.379 205.179,96.379 205.299,96.499 205.299,98.133 205.419,98.253 205.779,98.253 205.899,98.133 205.899,96.499 206.019,96.379 206.379,96.379 206.499,96.499 206.499,98.133 206.619,98.253 206.979,98.253 207.099,98.133 207.099,96.499 207.219,96.379 207.579,96.379 207.699,96.499 207.699,97.965 207.819,98.085 208.179,98.085 208.299,97.965 208.299,97.16 208.419,97.04 209.591,97.04 R238.2@211.06,97.04 211.979,96.121 211.979,94.63 212.819,93.79 214.19,93.79 U56.C4@214.75,94.35
  Bottom Layer w0.15: J4.13@197.09,97.04 J4B.7@202.17,97.04
QSPI_1_IO3: M1.B60 RA25.1 | length 10.6
  Top Layer w0.15: v1(117.571,81.65) 118.539,81.65 118.961,82.072 118.961,82.694 M1.B60@118.967,82.7
  Bottom Layer w0.15: RA25.1@114.975,88.25 114.925,88.2 114.925,83.482 115.475,82.932 116.702,82.932 117.557,82.078 117.557,81.664 v1(117.571,81.65)
QSPI_1_IO3_JMP: J4.15 J4B.8 U56.D4 | length 32.3
  Top Layer w0.15: J4B.8@202.17,99.58 203.506,99.58 203.581,99.58 203.701,99.7 203.701,100.019 203.821,100.139 204.181,100.139 204.301,100.019 204.301,99.081 204.421,98.961 204.781,98.961 204.901,99.081 204.901,100.019 205.021,100.139 205.381,100.139 205.501,100.019 205.501,99.081 205.621,98.961 205.981,98.961 206.101,99.081 206.101,100.019 206.221,100.139 206.581,100.139 206.701,100.019 206.701,99.081 206.821,98.961 207.181,98.961 207.301,99.081 207.301,100.019 207.421,100.139 207.781,100.139 207.901,100.019 207.901,99.081 208.021,98.961 208.381,98.961 208.501,99.081 208.501,100.019 208.621,100.139 208.981,100.139 209.101,100.019 209.101,99.081 209.221,98.961 209.581,98.961 209.701,99.081 209.701,99.783 209.821,99.903 210.181,99.903 210.301,99.783 210.301,99.7 210.421,99.58 211.362,99.58 211.718,99.58 212.481,98.817 212.481,95.817 213.448,94.85 214.25,94.85 U56.D4@214.75,95.35
  Bottom Layer w0.15: J4.15@197.09,99.58 J4B.8@202.17,99.58
QSPI_1_SCK: M1.B65 RA11.4 | length 6
  Top Layer w0.15: M1.B65@115.792,82.7 115.792,82.994 116.423,83.625 116.423,84.17 v1(116.44,84.186)
  Bottom Layer w0.15: RA11.4@116.134,88.25 116.118,88.233 116.118,84.613 116.44,84.291 v1(116.44,84.186)
QSPI_1_SCK_JMP: J4.7 J4B.4 U56.B2 | length 32.4
  Top Layer w0.15: J4B.4@202.139,89.389 J4B.4@202.17,89.42 203.25,90.5 203.587,90.5 203.663,90.5 203.783,90.62 203.783,90.917 203.903,91.037 204.262,91.037 204.382,90.917 204.382,89.771 204.502,89.651 204.862,89.651 204.982,89.771 204.982,90.917 205.102,91.037 205.462,91.037 205.582,90.917 205.582,89.771 205.702,89.651 206.062,89.651 206.182,89.771 206.182,90.917 206.302,91.037 206.662,91.037 206.782,90.917 206.782,89.771 206.902,89.651 207.262,89.651 207.382,89.771 207.382,90.917 207.502,91.037 207.862,91.037 207.982,90.917 207.982,90.165 208.102,90.045 208.462,90.045 208.582,90.165 208.582,90.38 208.702,90.5 209.152,90.5 209.512,90.14 215.578,90.14 217.36,91.923 217.36,92.74 U56.B2@216.75,93.35
  Bottom Layer w0.15: J4.7@197.09,89.42 J4B.4@202.17,89.42
R_GPIO_13: J6.19 J6A.10 RA27.8 | length 54.7
  Top Layer w0.15: RA27.8@161.203,72.928 161.203,67.307 164.071,64.439 168.279,64.439 170.411,66.571 170.411,68.711 171.558,69.858 176.866,69.858 182.451,64.274 182.451,63.529 188.165,57.815 190.411,57.815 190.9,57.326 190.9,55.37 J6A.10@189.47,53.94
  Bottom Layer w0.15: J6A.10@189.47,53.94 J6.19@194.55,53.94
R_GPIO_14: J6.17 J6A.9 RA27.7 | length 50.7
  Top Layer w0.15: RA27.7@160.703,72.928 160.703,67.296 163.96,64.039 168.629,64.039 170.871,66.281 170.871,68.571 171.807,69.507 176.707,69.507 181.52,64.694 181.52,63.23 188.27,56.48 J6A.9@189.47,56.48
  Bottom Layer w0.15: J6A.9@189.47,56.48 J6.17@194.55,56.48
R_I2C_4_SCL: J6.11 J6A.6 RA26.8 | length 46.6
  Top Layer w0.15: RA26.8@163.785,72.928 163.785,67.552 165.273,66.065 167.165,66.065 168.725,67.625 168.725,69.359 170.699,71.333 177.656,71.333 181.014,67.975 190.036,67.975 190.796,67.215 190.796,65.426 J6A.6@189.47,64.1
  Bottom Layer w0.15: J6A.6@189.47,64.1 J6.11@194.55,64.1
R_I2C_4_SDA: J6.9 J6A.5 RA26.7 | length 43
  Top Layer w0.15: RA26.7@163.286,72.928 163.286,66.915 164.596,65.604 167.652,65.604 169.123,67.076 169.123,69.159 170.919,70.954 177.361,70.954 181.675,66.64 J6A.5@189.47,66.64
  Bottom Layer w0.15: J6A.5@189.47,66.64 J6.9@194.55,66.64
R_I2C_5_SCL: J6.23 J6A.12 RA27.5 | length 54.8
  Top Layer w0.15: RA27.5@159.703,72.928 159.703,67.293 163.697,63.3 169.336,63.3 172.676,66.64 178.451,66.64 179.111,65.981 179.111,59.219 J6A.12@189.47,48.86
  Bottom Layer w0.15: J6A.12@189.47,48.86 J6.23@194.55,48.86
R_I2C_5_SDA: J6.21 J6A.11 RA27.6 | length 55.3
  Top Layer w0.15: RA27.6@160.203,72.928 160.203,67.305 163.846,63.663 168.963,63.663 171.286,65.986 171.286,68.39 172.026,69.13 176.516,69.13 180.434,65.211 180.434,60.436 J6A.11@189.47,51.4
  Bottom Layer w0.15: J6A.11@189.47,51.4 J6.21@194.55,51.4
RECOV#_1V8: Q9.5 U87.6 | length 139
  Top Layer w0.15: v1(45.515,134.291) U87.6@45.515,136.136 ; Q9.5@80.475,32.05 v1(80.475,34.675)
  INT2_SIG w0.15: v1(45.515,134.291) 45.515,131.602 50.89,126.227 53.58,126.227 56.4,123.406 56.4,86.352 57.152,85.6 61.4,85.6 64.05,82.95 64.05,30.376 64.806,29.62 70.008,29.62 75.063,34.675 v1(80.475,34.675)
RECOVERY_MICO#: J19.5 Q9.6 | length 12.4
  Top Layer w0.15: J19.5@78.469,22.445 80.8,24.776 80.8,27.725 81.95,28.875 81.95,30.65 81.275,31.325 80.325,31.325 79.975,31.675 Q9.6@79.975,32.05
RESET#_1V8: Q11.5 U87.4 | length 138.1
  Top Layer w0.15: v1(44.215,134.291) U87.4@44.215,136.136 ; Q11.5@78.095,32.05 v1(78.095,33.125)
  INT2_SIG w0.15: v1(44.215,134.291) 44.227,134.279 44.227,130.588 49.98,124.835 52.949,124.835 54.847,122.938 54.847,85.516 56.363,84 61.05,84 62.4,82.65 62.4,29.121 63.121,28.4 71.069,28.4 75.794,33.125 v1(78.095,33.125)
RESET_MICO#: J19.1 Q11.6 | length 19.3
  Top Layer w0.15: Q11.6@77.595,32.05 77.595,31.8 77.97,31.425 78.97,31.425 79.22,31.175 79.22,28.409 77.345,26.535 77.345,21.666 77.811,21.2 79.25,21.2 80.05,20.4 80.05,18.946 J19.1@78.469,17.365
RS485_A: J20.1 J66.2 R348.1 | length 15.6
  Top Layer w0.15: R348.1@178.875,182.15 178.875,183.517 179.387,184.029 179.387,186.167 J66.2@180.145,186.925 179.355,187.715 179.355,193.605 J20.1@181.7,195.95
RS485_B: J20.2 R349.1 R350.2 | length 16.2
  Top Layer w0.15: J20.2@176.7,195.95 178.973,193.677 178.973,184.283 177.855,183.165 R349.1@177.855,182.15 R350.2@176.855,182.15
SD_1_CD#: J30.10 M1.A01 U17.4 | length 105
  Top Layer w0.15: M1.A01@156.433,84.9 156.433,84.887 156.991,84.329 v1(156.991,84.315)
  INT2_SIG w0.18: v1(156.413,65.574) 156.413,65.62 157.116,65.62 160.017,68.521 160.017,76.109 157.475,78.651 157.475,83.831 v1(156.991,84.315)
  Bottom Layer w0.15: J30.10@119.53,22.525 119.53,25.27 118.48,26.32 U17.4@117.475,26.32 117.475,27.02 118.48,28.025 118.48,30.893 118.926,31.339 119.403,31.816 119.573,31.816 120.178,31.21 120.348,31.21 120.603,31.465 120.603,31.635 119.997,32.24 119.997,32.41 120.252,32.664 120.421,32.664 121.027,32.059 121.197,32.059 121.451,32.314 121.451,32.483 120.846,33.089 120.846,33.258 121.1,33.513 121.27,33.513 121.875,32.908 122.045,32.908 122.3,33.162 122.3,33.332 121.694,33.937 121.694,34.107 121.949,34.361 122.119,34.361 122.724,33.756 122.894,33.756 123.148,34.011 123.148,34.18 122.543,34.786 122.543,34.955 122.797,35.21 122.967,35.21 123.572,34.605 123.742,34.605 123.997,34.859 123.997,35.029 123.391,35.634 123.391,35.804 123.646,36.059 123.816,36.059 124.421,35.453 124.591,35.453 124.845,35.708 124.845,35.877 124.24,36.483 124.24,36.653 124.494,36.907 124.664,36.907 125.27,36.302 125.439,36.302 125.694,36.556 125.694,36.726 125.088,37.331 125.088,37.501 125.343,37.756 125.513,37.756 126.118,37.15 126.288,37.15 126.542,37.405 126.542,37.574 125.937,38.18 125.937,38.35 126.191,38.604 126.361,38.604 126.967,37.999 127.136,37.999 127.391,38.253 127.391,38.423 126.785,39.028 126.785,39.198 127.04,39.453 127.21,39.453 127.815,38.847 127.985,38.847 128.239,39.102 128.239,39.271 127.634,39.877 127.634,40.047 127.888,40.301 128.058,40.301 128.203,40.156 128.373,40.156 128.628,40.411 128.628,40.58 128.482,40.725 128.482,40.895 128.701,41.114 148.608,61.021 150.567,61.021 155.167,65.62 156.367,65.62 v1(156.413,65.574)
SD_1_CLK: J30.5 M1.A05 U17.1 | length 106.3
  Top Layer w0.15: v1(151.024,90.081) 151.024,89.345 153.893,86.476 M1.A05@153.893,84.9
  Bottom Layer w0.15: J30.5@111.6,22.525 112.025,22.95 112.025,23.35 114.075,25.4 114.075,27.85 115.055,28.83 U17.1@115.575,28.83 115.575,34.366 116.434,35.225 116.487,35.278 116.487,35.447 116.04,35.894 116.04,36.063 116.295,36.318 116.465,36.318 117.55,35.233 117.72,35.233 117.974,35.487 117.974,35.657 116.889,36.742 116.889,36.912 117.143,37.167 117.313,37.167 118.398,36.081 118.568,36.081 118.823,36.336 118.823,36.505 117.737,37.591 117.737,37.761 117.992,38.015 118.162,38.015 119.247,36.93 119.417,36.93 119.671,37.184 119.671,37.354 118.735,38.29 118.735,38.46 118.99,38.714 119.159,38.714 119.456,38.417 119.626,38.417 120.484,39.275 120.809,39.6 125.278,39.6 145.5,59.822 145.5,76.957 145.106,77.351 145.106,80.326 144.454,80.977 144.454,84.754 145.002,85.302 145.002,86.396 147.783,89.177 148.994,89.177 149.823,90.006 150.949,90.006 v1(151.024,90.081)
SD_1_CMD: J30.2 M1.A07 U18.6 | length 106.3
  Top Layer w0.15: v1(150.214,90.531) 150.26,90.485 150.26,87.977 152.623,85.614 M1.A07@152.623,84.9
  Bottom Layer w0.15: J30.2@104.1,22.525 U18.6@104.1,26.32 104.1,27.175 104.275,27.35 106.25,27.35 106.75,27.85 106.75,33.93 109.325,36.505 109.803,36.983 109.972,36.983 110.387,36.568 110.557,36.568 110.811,36.822 110.811,36.992 110.362,37.441 110.362,37.611 110.617,37.865 110.787,37.865 111.057,37.595 111.227,37.595 111.482,37.849 111.482,38.019 111.245,38.255 111.245,38.425 111.548,38.728 112.929,40.109 125.151,40.109 145.05,60.008 145.05,76.588 144.62,77.018 144.62,80.048 144.004,80.664 144.004,84.977 144.466,85.438 144.466,86.497 147.597,89.627 148.808,89.627 149.689,90.509 150.192,90.509 v1(150.214,90.531)
SD_1_D0: J30.7 M1.A03 U17.3 | length 106.3
  Top Layer w0.15: v1(151.875,89.72) 151.875,89.692 155.163,86.405 M1.A03@155.163,84.9
  Bottom Layer w0.15: J30.7@116.6,22.525 116.6,23.625 114.625,25.6 114.625,27.225 115.2,27.8 116.75,27.8 117.475,28.525 U17.3@117.475,28.83 117.475,32.745 117.772,33.042 117.825,33.095 117.825,33.265 117.504,33.586 117.504,33.756 117.759,34.011 117.928,34.011 118.637,33.302 118.807,33.302 119.061,33.557 119.061,33.726 118.353,34.435 118.353,34.605 118.607,34.859 118.777,34.859 119.485,34.15 119.655,34.15 119.91,34.405 119.91,34.575 119.201,35.283 119.201,35.453 119.456,35.708 119.625,35.708 120.334,34.999 120.504,34.999 120.758,35.254 120.758,35.423 120.05,36.132 120.05,36.302 120.304,36.556 120.474,36.556 121.183,35.848 121.352,35.848 121.607,36.102 121.607,36.272 120.898,36.98 120.898,37.15 121.153,37.405 121.322,37.405 122.031,36.696 122.201,36.696 122.455,36.951 122.455,37.12 121.747,37.829 121.747,37.999 122.001,38.253 122.171,38.253 122.818,37.606 122.988,37.606 123.242,37.861 123.242,38.03 123.086,38.187 123.086,38.356 123.395,38.665 123.73,39 125.315,39 146.175,59.86 146.175,82.009 145.95,82.234 145.95,84.097 146.589,84.736 146.589,87.347 147.97,88.727 149.181,88.727 150.009,89.556 151.589,89.556 151.753,89.72 v1(151.875,89.72)
SD_1_D1: J30.8 M1.A02 U17.6 | length 106.3
  Top Layer w0.15: v1(153.237,89.106) 155.798,86.545 M1.A02@155.798,84.9
  Bottom Layer w0.15: J30.8@118.23,22.525 118.23,24.106 117.836,24.5 116.6,24.5 115.575,25.525 U17.6@115.575,26.32 115.575,27.262 115.663,27.35 117.166,27.35 117.99,28.174 117.99,31.039 146.625,59.674 146.625,65.355 146.625,66.03 146.745,66.15 149.031,66.15 149.151,66.27 149.151,66.63 149.031,66.75 146.745,66.75 146.625,66.87 146.625,67.23 146.745,67.35 149.031,67.35 149.151,67.47 149.151,67.83 149.031,67.95 146.745,67.95 146.625,68.07 146.625,68.43 146.745,68.55 148.585,68.55 148.705,68.67 148.705,69.03 148.585,69.15 146.745,69.15 146.625,69.27 146.625,69.816 146.625,82.347 146.4,82.572 146.4,83.911 147.039,84.55 147.039,87.161 148.156,88.277 149.367,88.277 150.195,89.106 v1(153.237,89.106)
SD_1_D2: J30.9 M1.A10 U18.1 | length 106.3
  Top Layer w0.15: v1(148.6,91.05) 148.6,88.364 150.718,86.247 M1.A10@150.718,84.9
  Bottom Layer w0.15: J30.9@99.1,22.525 99.1,24.614 103.316,28.83 U18.1@104.1,28.83 104.1,33.5 111.609,41.009 124.778,41.009 144.15,60.381 144.15,76.215 143.6,76.765 143.6,79.796 143.105,80.291 143.105,81.941 142.469,82.577 142.469,86.005 147.514,91.05 v1(148.6,91.05)
SD_1_D3: J30.1 M1.A08 U18.3 | length 106.3
  Top Layer w0.15: v1(149.51,91.092) 149.56,91.042 149.56,88.04 151.988,85.613 M1.A08@151.988,84.9
  Bottom Layer w0.15: J30.1@101.6,22.525 101.6,25.82 103.58,27.8 105.725,27.8 106,28.075 U18.3@106,28.83 106,33.885 112.674,40.559 124.965,40.559 144.6,60.195 144.6,76.402 144.17,76.831 144.17,79.862 143.555,80.477 143.555,82.335 142.919,82.97 142.919,85.819 147.178,90.077 148.496,90.077 v1(149.51,91.092)
SD_1_PWR_EN: M1.A06 R210.2 R460.1 | length 94
  Top Layer w0.15: v1(152.965,86.405) 153.258,86.112 M1.A06@153.258,84.9
  INT2_SIG w0.15: v1(110.95,34.792) 110.95,36.838 131.716,57.604 132.486,57.604 134.775,55.315 142.672,55.315 143.966,56.609 149.553,56.609 161.115,68.171 161.115,81.232 155.942,86.405 v1(152.965,86.405)
  Bottom Layer w0.15: R210.2@110.95,32.835 R460.1@110.95,33.8 v1(110.95,34.792)
SHLD1: H1.0 R447.1 | length 5.2
  Top Layer w0.15: H1.0@5,5 R447.1@5,10.15
SHLD2: H2.0 R448.1 | length 4.2
  Top Layer w0.25: R448.1@4.975,190.85 5,190.875 H2.0@5,195
SHLD3: H3.0 R449.1 | length 4.1
  Top Layer w0.25: R449.1@245,190.9 H3.0@245,195
SHLD4: H4.0 R11.1 | length 4.4
  Top Layer w0.25: H4.0@245,5 R11.1@245,9.425
SMBALERT#: J54.4 R266.2 U58.14 | length 28.2
  Top Layer w0.15: R266.2@155.024,40.712 155.525,40.712 156.16,41.347 158.277,41.347 158.436,41.189 158.436,32.64 161.329,29.747 161.329,25.386 162.44,24.275 166.67,24.275 J54.4@167.87,23.075
SPI_1_CLK: M1.D12 RA28.4 | length 4.6
  Top Layer w0.15: RA28.4@147.85,74.15 147.85,75.016 149.447,76.613 M1.D12@149.447,78.1
SPI_1_CLK_JMP: J2.2 J2B.1 | length 5.1
  Bottom Layer w0.15: J2B.1@52.68,31.16 J2.2@57.76,31.16
SPI_1_CS: M1.D09 RA28.1 | length 4.8
  Top Layer w0.15: RA28.1@149.35,74.15 149.383,74.183 149.383,74.635 151.352,76.605 M1.D09@151.352,78.1
SPI_1_CS_JMP: J2.4 J2B.2 | length 5.1
  Bottom Layer w0.15: J2B.2@52.68,33.7 J2.4@57.76,33.7
SPI_1_MISO: M1.D10 RA28.2 | length 4.7
  Top Layer w0.15: RA28.2@148.85,74.15 148.85,74.743 150.717,76.61 M1.D10@150.717,78.1
SPI_1_MISO_JMP: J2.6 J2B.3 | length 5.1
  Bottom Layer w0.15: J2B.3@52.68,36.24 J2.6@57.76,36.24
SPI_1_MOSI: M1.D11 RA28.3 | length 4.7
  Top Layer w0.15: RA28.3@148.35,74.15 148.35,74.88 150.082,76.612 M1.D11@150.082,78.1
SPI_1_MOSI_JMP: J2.8 J2B.4 | length 5.1
  Bottom Layer w0.15: J2B.4@52.68,38.78 J2.8@57.76,38.78
SPI_2_CLK: M1.D14 RA31.1 | length 4.5
  Top Layer w0.15: RA31.1@146.733,74.15 146.733,75.778 148.177,77.222 M1.D14@148.177,78.1
SPI_2_CLK_JMP: J2.10 J2B.5 | length 5.1
  Bottom Layer w0.15: J2B.5@52.68,41.32 J2.10@57.76,41.32
SPI_2_CS: M1.D16 RA31.3 | length 4.4
  Top Layer w0.15: RA31.3@145.733,74.15 145.733,76.096 146.907,77.27 M1.D16@146.907,78.1
SPI_2_CS_JMP: J2.12 J2B.6 | length 5.1
  Bottom Layer w0.15: J2B.6@52.68,43.86 J2.12@57.76,43.86
SPI_2_MISO: M1.D15 RA31.2 | length 4.5
  Top Layer w0.15: RA31.2@146.233,74.15 146.233,74.831 146.211,74.854 146.211,75.661 146.233,75.684 146.233,75.915 147.542,77.223 M1.D15@147.542,78.1
SPI_2_MISO_JMP: J2.14 J2B.7 | length 5.1
  Bottom Layer w0.15: J2B.7@52.68,46.4 J2.14@57.76,46.4
SPI_2_MOSI: M1.D17 RA31.4 | length 4.4
  Top Layer w0.15: RA31.4@145.233,74.15 145.233,76.275 146.272,77.313 M1.D17@146.272,78.1
SPI_2_MOSI_JMP: J2.16 J2B.8 | length 5.1
  Bottom Layer w0.15: J2B.8@52.68,48.94 J2.16@57.76,48.94
SS_DIR_SEL: R401.1 U96.9 X104.1 | length 12.4
  Top Layer w0.2: R401.1@112.6,171.8 112.6,172.296 112.773,172.468 v1(112.773,172.988)
  INT3_SIG w0.15: X104.1@107.71,179.622 108.736,179.622 112.773,175.586 v1(112.773,172.988)
  Bottom Layer w0.15: U96.9@107.71,177.775 X104.1@107.71,179.622
SSRX1_N: J32.B10 L22.3 U20.1 U20.10 | length 11
  Top Layer w0.15: v4(134.925,193.375) 134.925,193.458 135.105,193.638 135.105,193.887 135.075,193.917 135.075,194.175 J32.B10@135,194.25 ; L22.3@137.65,187.125 137.575,187.2 137.575,187.285 137.547,187.313 137.547,188.007 137.635,188.096 137.635,188.471 137.535,188.571 137.535,188.83 137.635,188.93 137.635,189.304 137.535,189.404 137.535,191.468 137.673,191.605 137.877,191.605 138.102,191.38 v1(138.19,191.38)
  Bottom Layer w0.15: 135.11,193.112 134.925,193.297 v4(134.925,193.375) 134.925,193.312 135.125,193.112 135.125,192.798 135.5,192.422 136.094,192.422 136.911,191.605 137.877,191.605 138.102,191.38 v1(138.19,191.38)
SSRX1_P: J32.B11 L22.4 U20.2 U20.9 | length 11
  Top Layer w0.15: J32.B11@135.5,194.25 135.425,194.175 135.425,193.907 135.405,193.887 135.405,193.638 135.573,193.47 135.625,193.47 v4(135.625,193.375) ; L22.4@137.15,187.125 137.225,187.2 137.225,187.291 137.247,187.313 137.247,187.984 137.135,188.096 137.135,188.471 137.235,188.571 137.235,188.83 137.135,188.93 137.135,189.305 137.235,189.405 137.235,191.592 137.548,191.905 137.877,191.905 138.102,192.13 v1(138.19,192.13)
  Bottom Layer w0.15: 135.44,193.112 135.625,193.297 v4(135.625,193.375) 135.625,193.312 135.425,193.112 135.425,192.922 135.625,192.722 136.218,192.722 137.035,191.905 137.877,191.905 138.102,192.13 v1(138.19,192.13)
